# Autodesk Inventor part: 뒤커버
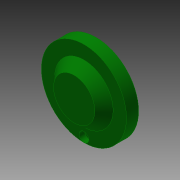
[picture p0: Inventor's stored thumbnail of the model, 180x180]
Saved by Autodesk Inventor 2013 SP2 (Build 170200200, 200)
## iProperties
Created: 2017-08
Part Number: 뒤커버
Material: 알루미늄 6061
Document SubType Name: Modeling
Designer: mduedu
Density: 1 g/cm^3
Author: mduedu
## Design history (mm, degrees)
sketch "스케치1"
  geometry: C1 r 35 at (0, 0); 1 further point
  constraints: 1 centre point, 1 coincident
  dimensions: "d0" = 70 diameter of C1
extrude "돌출1" new body sketch "스케치1" distance "d1" = 10; taper "d2" = 0 deg
sketch "스케치2"
  geometry: C1 r 24 at (0, 0); 1 further point
  constraints: 1 centre point, 1 coincident
  dimensions: "d3" = 48 diameter of C1
node "작업 평면1"
sketch "스케치3"
  geometry: C1 r 17 at (0, 0); 1 further point
  constraints: 1 centre point, 1 coincident
  dimensions: "d5" = 34 diameter of C1
feature "로프트1" sketch "스케치3" dims "d6" = 0, "d7" = 90 deg, "d8" = 0, "d9" = 90 deg
sketch "스케치4"
  geometry: C1 r 24 at (0, 0) reference; 1 further point
extrude "돌출2" join sketch "스케치4" distance "d10" = 8; taper "d11" = 0 deg
hole "구멍1" diameter "d14" = 40; stored, may be unused: countersink angle "d18" = 90 deg, drill point angle "d20" = 0 deg; dims "d12" = 10, "d13" = 10, "d15" = 6, "d16" = 4, "d17" = 2, "d19" = 12
hole "구멍2" diameter "d23" = 34; stored, may be unused: countersink angle "d27" = 90 deg, drill point angle "d29" = 0 deg; dims "d24" = 6, "d25" = 4, "d26" = 2, "d28" = 6, "d62" = 10, "d63" = 10
chamfer "모따기1" distance "d39" = 1; stored, may be unused: second distance "d40" = 2, angle "d41" = 45 deg
fillet "모깎기1" dims "d42" = 0.3
fillet "모깎기2" dims "d43" = 3
fillet "모깎기3" dims "d56" = 3
sketch "스케치5" dims "d44" = 58
  geometry: 6 further points
  constraints: 2 vertical alignment, 1 coincident, 7 other
  dimensions: "d47" = 360 deg dimension on point (0, 0) point (0, 29) (derived)
sketch "스케치6" dims "d72" = 62
  geometry: C1 r 35 at (0, 0) reference; 2 further points
  constraints: 2 vertical alignment, 1 coincident, 2 other
hole "구멍4" sketch "스케치6" at (0, -31) diameter "d49" = 4.5; stored, may be unused: countersink angle "d53" = 90 deg, drill point angle "d55" = 0 deg; dims "d50" = 6, "d51" = 8, "d52" = 4.6, "d54" = 8
fillet "모깎기4" dims "d57" = 3
fillet "모깎기5" dims "d58" = 3
sketch "스케치7"
  geometry: L1 (-4, -31)-(4, -31); L2 (4, -31)-(4, -38); L3 (4, -38)-(-4, -38); L4 (-4, -38)-(-4, -31); 2 further points
  constraints: 8 end point, 2 parallel, 2 vertical, 1 horizontal, 1 midpoint, 1 perpendicular, 1 vertical alignment
  dimensions: "d65" = 7 distance of L1.end L2.end
extrude "돌출3" cut sketch "스케치7" stored distance "d67" = 10; taper "d68" = 0 deg
node "솔리드1"
pattern_circular "원형 패턴2" dims angle "d76" = 360 deg
pattern_circular "원형 패턴1" dims angle "d70" = 360 deg
other parameters: "d4" = 8
